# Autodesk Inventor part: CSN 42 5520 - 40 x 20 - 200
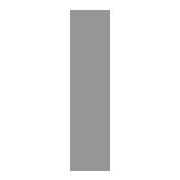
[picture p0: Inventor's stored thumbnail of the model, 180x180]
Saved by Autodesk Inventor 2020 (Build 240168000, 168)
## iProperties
Created: 2019-01
Part Number: CSN 42 5520 - 40 x 20 - 200
Material: Ocel
Description: Tyč
Document SubType Name: Modeling
Standard: CSN 42 5520
Designer: doma
Standards Organization: CSN
Language: cs-CZ
Size Designation: 40 x 20 - 200
Categories: <MemberInstance><Categories><Category DisplayName="Konstrukční profily" InternalName="089c4875-fa83-4c05-b084-43b9cc11f5ed" Mnemonic="GRDR"><CategoryParameter D
Stock Number: 40 x 20
Density: 7.85 g/cm^3
Appearance: Plech
Mass: 1256 g
Surface Area: 256 cm^2
Volume: 160 cm^3
IsCustomPart: 1
G_L: 200.000 mm
Author: doma
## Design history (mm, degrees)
node "Počáteční rovina"
node "Koncová rovina"
sketch "Náčrt"
  geometry: L1 (10, -20)-(-10, -20); L2 (-10, -20)-(-10, 20); L3 (-10, 20)-(10, 20); L4 (10, 20)-(10, -20); L5 (-6, 0)-(8, 0); L6 (0, -30)-(0, 40); L7 (0, 54)-(0, -44) reference; L8 (-9.2, 0)-(13.2, 0) reference
  constraints: 12 end point, 2 collinear, 2 parallel, 1 horizontal, 1 perpendicular
  dimensions: "d0" = 40 distance between parallel lines of L3 L1 (= G_W); "d1" = 20 distance between parallel lines of L4 L2 (= G_H); "d4" = 10 distance between parallel lines of L6 L4 (= 0.5 x d1); "d5" = 20 distance between parallel lines of L5 L3 (= 0.5 x d0)
extrude "Těleso" new body sketch "Náčrt" stored distance "d2" = 200 (= G_L); taper "d3" = 0 deg
node "Driven Length"
  sketch "Sketch3"
    geometry: L1 (0, 0)-(10, 0) reference
    constraints: 2 end point, 1 horizontal
  workplane "Work Plane3"
  sketch "Sketch4"
    geometry: L1 (-2, 0)-(12, 0) reference; L2 (-2, 200)-(12, 200) reference
    dimensions: "d9" = 200 distance between parallel lines of L1 L2 (derived)
body "Solid1"
other parameters: "G_W" = 40 [user parameter; used in 1 equation term], "G_H" = 20 [user parameter; used in 1 equation term], "G_L" = 200 (= d9) [user parameter; used in 1 equation term], "G_OFFSET_START" = 0 [user parameter; used in 1 equation term], "G_OFFSET_END" = 0 [user parameter; used in 1 equation term], "d6" = 0 (computed from G_OFFSET_START), "d8" = 90 deg
